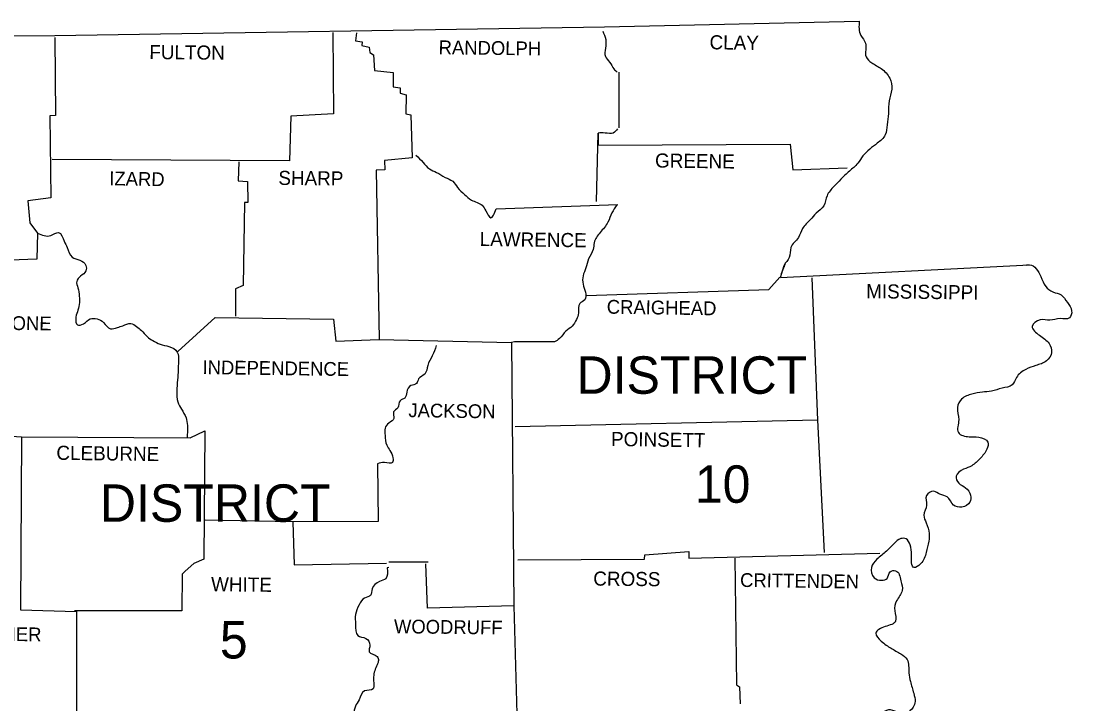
# Model space of a CAD drawing. Extents: x 21307 to 29830, y 1322443 to 1332359.
# Drawn here: x 25498.6 to 25818.7, y 1326299.6 to 1326507.6 of the extents above; entities that cross this region are included whole.
import ezdxf

# ---------------------------------------------------------------- set-up
doc = ezdxf.new("R2010")
doc.units = 0
doc.layers.add('R_Draft', color=7, linetype='Continuous')

msp = doc.modelspace()

# ---------------------------------------------------------------- linework, layer by layer
at = {"layer": 'R_Draft'}
for p, q in [((25729.86, 1326429.5), (25731.06, 1326433.2)), ((25730.16, 1326430.7), (25731.36, 1326433.6)), ((25610.66, 1326342.9), (25622.56, 1326342.9))]:
    msp.add_line(p, q, dxfattribs=at)
for points in [[(25205.26, 1326503), (25366.96, 1326502.9), (25508.86, 1326503.2), (25676.26, 1326505.8), (25753.86, 1326507.6)], [(25593.56, 1326504.1), (25593.76, 1326479.3), (25580.76, 1326478.6), (25580.36, 1326465), (25508.06, 1326465.4)], [(25600.76, 1326504), (25600.46, 1326501.6), (25602.46, 1326501.3), (25602.36, 1326500.1), (25604.66, 1326499.6), (25604.86, 1326498), (25605.96, 1326497.3), (25606.26, 1326492.5), (25611.96, 1326491.9), (25611.96, 1326487.6), (25614.06, 1326487.3), (25614.06, 1326485.6), (25615.86, 1326485.1), (25615.76, 1326479.3), (25617.36, 1326479), (25617.76, 1326465.9), (25609.26, 1326465.1), (25609.36, 1326462.3), (25606.76, 1326462.2), (25607.66, 1326410.6), (25647.96, 1326409.7), (25648.66, 1326329.5), (25622.36, 1326328.8), (25621.86, 1326342.3)], [(25508.86, 1326502.6), (25509.06, 1326478.8), (25507.36, 1326478.7), (25507.66, 1326453.8), (25500.66, 1326452.8), (25501.26, 1326446.1), (25503.66, 1326443), (25503.46, 1326435.1), (25489.86, 1326434.6), (25489.36, 1326422.4), (25476.96, 1326422), (25476.36, 1326407.2), (25477.06, 1326406), (25477.36, 1326382.4), (25498.76, 1326381), (25498.46, 1326328.3), (25515.46, 1326327.8), (25515.46, 1326274.2), (25502.06, 1326273.2), (25501.06, 1326261.4), (25478.56, 1326261.3)], [(25680.66, 1326492), (25680.66, 1326475.1)], [(25673.86, 1326452.6), (25674.36, 1326473.5), (25674.36, 1326469.8), (25732.86, 1326470.1), (25733.66, 1326462.3), (25750.16, 1326462.9)], [(25564.96, 1326464.7), (25564.76, 1326458.9), (25567.56, 1326458.7), (25567.66, 1326452.3), (25566.66, 1326452.3), (25566.26, 1326427.1), (25563.96, 1326426.1), (25563.96, 1326417.7)], [(25643.26, 1326450.4), (25680.36, 1326451.7)], [(25729.86, 1326429.5), (25805.76, 1326433.4)], [(25670.86, 1326424), (25726.36, 1326425.8), (25729.66, 1326429.6)], [(25739.46, 1326429.4), (25741.16, 1326386.1), (25743.16, 1326345.8)], [(25546.36, 1326407), (25557.76, 1326417.3), (25593.76, 1326416.8), (25594.46, 1326410.1), (25607.56, 1326410.6)], [(25661.06, 1326409.9), (25648.86, 1326409.9), (25647.96, 1326409.7)], [(25741.16, 1326386.1), (25649.06, 1326384)], [(25498.76, 1326381), (25550.16, 1326380.7), (25554.56, 1326382.8), (25554.26, 1326343.7), (25551.26, 1326342.4), (25548.56, 1326340.1), (25547.66, 1326339.2), (25547.56, 1326328), (25514.86, 1326328)], [(25607.16, 1326372.8), (25607.36, 1326355.2), (25581.36, 1326355.1), (25554.66, 1326355.6)], [(25581.36, 1326355.1), (25581.76, 1326342), (25609.86, 1326342.5)], [(25649.86, 1326343.5), (25688.46, 1326343.7), (25688.56, 1326345.1), (25701.96, 1326346.1), (25701.96, 1326344), (25760.16, 1326345.6)], [(25715.96, 1326344), (25716.46, 1326305.5), (25717.36, 1326304.9), (25717.66, 1326299.7)], [(25715.96, 1326344), (25716.46, 1326305.5), (25717.36, 1326304.9), (25717.66, 1326299.7)], [(25715.96, 1326344), (25716.46, 1326305.5), (25717.36, 1326304.9), (25717.66, 1326299.7)], [(25715.96, 1326344), (25716.46, 1326305.5), (25717.36, 1326304.9), (25717.66, 1326299.7)], [(25715.96, 1326344), (25716.46, 1326305.5), (25717.36, 1326304.9), (25717.66, 1326299.7)], [(25610.66, 1326341.2), (25610.16, 1326341.1)], [(25648.66, 1326329.5), (25650.16, 1326274.7), (25626.36, 1326274.6), (25626.26, 1326272.4), (25619.36, 1326272), (25618.76, 1326260.6), (25610.36, 1326260.6)]]:
    msp.add_lwpolyline(points, dxfattribs=at)
for points in [[(25753.86, 1326507.6), (25754.36, 1326503.2), (25755.76, 1326500.9), (25755.96, 1326496.7), (25757.66, 1326494.9), (25760.56, 1326493.1), (25763.16, 1326490.2), (25763.76, 1326486.8), (25762.96, 1326483.3), (25762.76, 1326479.4), (25762.36, 1326476), (25761.76, 1326472.9), (25759.36, 1326470.4), (25757.06, 1326468.6), (25754.96, 1326466.5), (25753.46, 1326464.3), (25750.86, 1326461.9), (25748.26, 1326459.4), (25746.16, 1326457.2), (25744.06, 1326454.4), (25743.06, 1326451.3), (25740.76, 1326449.1), (25738.96, 1326447.1), (25736.56, 1326444.4), (25735.36, 1326441.7), (25733.06, 1326438.6), (25732.56, 1326435.6), (25731.06, 1326433.2), (25730.96, 1326432.8)], [(25675.76, 1326504.5), (25676.66, 1326502), (25676.56, 1326499.3), (25676.56, 1326496.8), (25677.86, 1326495.1), (25679.16, 1326493), (25680.16, 1326492.1)], [(25680.26, 1326474.8), (25678.96, 1326473.5), (25676.46, 1326473.5), (25674.36, 1326473.5)], [(25618.86, 1326466.8), (25621.06, 1326464.5), (25622.96, 1326462.6), (25625.16, 1326461.5), (25627.76, 1326460), (25630.06, 1326458.8), (25631.56, 1326456.9), (25633.66, 1326454.8), (25635.76, 1326453.1), (25639.06, 1326451.5), (25640.16, 1326449.8), (25641.66, 1326447.7), (25643.26, 1326450.4)], [(25680.06, 1326451.6), (25678.56, 1326449.2), (25677.36, 1326446.4), (25674.96, 1326443.2), (25673.16, 1326440.1), (25672.86, 1326438), (25671.46, 1326435.2), (25670.66, 1326432.4), (25669.76, 1326430), (25669.76, 1326427.5), (25670.46, 1326425), (25670.26, 1326422.7), (25668.76, 1326421.6), (25668.36, 1326418.7), (25667.76, 1326416.7), (25666.46, 1326414.7), (25664.56, 1326413.2), (25662.56, 1326410.9), (25661.06, 1326409.9)], [(25503.66, 1326443), (25507.66, 1326442.3), (25510.06, 1326443.2), (25511.76, 1326440.6), (25512.66, 1326438.6), (25514.16, 1326435.7), (25516.56, 1326434.8), (25518.36, 1326433.2), (25518.36, 1326431.5), (25516.76, 1326429.9), (25515.56, 1326428.3), (25515.96, 1326426.4), (25516.36, 1326423.8), (25516.36, 1326421.3), (25515.76, 1326419), (25515.26, 1326416.9), (25515.76, 1326415.1), (25517.66, 1326415.4), (25519.66, 1326416.9), (25521.76, 1326416.9), (25523.76, 1326415.8), (25525.86, 1326413.9), (25527.96, 1326414.3), (25529.66, 1326414.8), (25532.06, 1326415.5), (25533.76, 1326414.6), (25535.26, 1326413.4), (25537.06, 1326411.5), (25538.76, 1326410.3), (25540.96, 1326409.2), (25543.66, 1326408.5), (25546.16, 1326406.8), (25546.56, 1326403.9), (25546.46, 1326401.4), (25546.26, 1326398.3), (25546.06, 1326394.9), (25546.36, 1326391.6), (25547.46, 1326389.4), (25548.86, 1326386.8), (25549.26, 1326384.4), (25549.16, 1326380.6)], [(25804.66, 1326433.3), (25805.76, 1326433.4), (25809.16, 1326429.8), (25810.66, 1326426.8), (25812.86, 1326425.1), (25815.36, 1326424.2), (25817.26, 1326421.9), (25818.56, 1326419.4), (25817.86, 1326417.2), (25815.06, 1326417), (25811.96, 1326416.5), (25808.96, 1326416.6), (25806.56, 1326414.6), (25808.76, 1326411.9), (25811.66, 1326409.4), (25812.46, 1326406.7), (25810.86, 1326404.1), (25807.66, 1326402.7), (25804.56, 1326401.5), (25801.76, 1326399.1), (25800.46, 1326396.8), (25797.36, 1326395.8), (25794.16, 1326394.9), (25791.36, 1326394.6), (25788.16, 1326394), (25785.06, 1326392.5), (25783.76, 1326389.9), (25784.16, 1326386.2), (25784.06, 1326382.3), (25787.36, 1326381), (25790.26, 1326380.9), (25793.06, 1326379.4), (25792.76, 1326377.2), (25790.66, 1326374.4), (25788.16, 1326372.2), (25785.66, 1326371.1), (25783.36, 1326369), (25784.16, 1326366.9), (25786.26, 1326365.5), (25787.76, 1326363.2), (25787.56, 1326361.1), (25785.16, 1326359.6), (25782.56, 1326360.2), (25780.66, 1326362.7), (25778.46, 1326363.5), (25776.56, 1326364.4), (25774.36, 1326363.1), (25774.36, 1326360.2), (25773.56, 1326357.1), (25774.26, 1326354.8), (25775.16, 1326351.6), (25775.06, 1326349.2), (25774.26, 1326345.8), (25772.56, 1326342.3), (25770.56, 1326341.2), (25769.76, 1326345), (25769.36, 1326348.1), (25768.16, 1326349.9), (25766.56, 1326350), (25764.46, 1326348.5), (25762.16, 1326346.2), (25759.26, 1326343.7), (25757.56, 1326341.2), (25758.46, 1326338.1), (25760.66, 1326337.3), (25762.36, 1326337.9), (25763.26, 1326339.9), (25764.96, 1326340.2), (25766.56, 1326337.1)], [(25625.06, 1326408.8), (25623.86, 1326405.7), (25622.46, 1326402.7), (25621.56, 1326400.1), (25619.66, 1326398.6), (25619.06, 1326397.2), (25617.36, 1326396.6), (25616.06, 1326394.6), (25615.46, 1326392.8), (25614.06, 1326392), (25613.36, 1326389.8), (25612.06, 1326388.6), (25612.16, 1326386.6), (25610.66, 1326385.2), (25609.46, 1326383.6), (25609.46, 1326381.4), (25609.96, 1326378.5), (25610.96, 1326376.8), (25611.86, 1326374.6), (25611.76, 1326373.2), (25609.26, 1326373.2), (25607.16, 1326372.8)], [(25610.16, 1326341.1), (25609.66, 1326337.8), (25607.76, 1326336.9), (25605.56, 1326334.7), (25605.06, 1326332.7), (25603.26, 1326331.9), (25601.56, 1326329.8), (25600.46, 1326326.9), (25600.46, 1326323.9), (25601.16, 1326320.5), (25603.66, 1326319.6), (25604.86, 1326317.6), (25604.66, 1326315.5), (25607.06, 1326314.1), (25607.46, 1326312.9), (25607.06, 1326311.6), (25605.96, 1326307.9), (25606.06, 1326305.4), (25605.86, 1326304.3), (25603.16, 1326303.6), (25601.56, 1326300.9), (25600.46, 1326299), (25600.06, 1326296.5), (25600.36, 1326294.7), (25599.56, 1326293.3), (25599.26, 1326291.2), (25598.26, 1326289.4), (25597.36, 1326287.7), (25598.36, 1326285.7), (25598.06, 1326284.3), (25597.46, 1326282.1), (25597.96, 1326281.4)], [(25766.56, 1326337.1), (25766.96, 1326334.2), (25765.26, 1326331.1), (25764.66, 1326328), (25764.96, 1326324.9), (25761.76, 1326323.2), (25758.96, 1326321.2), (25760.56, 1326318.8), (25763.56, 1326316.6), (25766.56, 1326314.9), (25768.46, 1326313.2), (25768.96, 1326309.1), (25769.46, 1326306.5), (25770.46, 1326302.9), (25770.86, 1326300.4), (25769.06, 1326297.4), (25766.96, 1326296.8), (25764.76, 1326297.5), (25762.16, 1326297.7), (25760.06, 1326295.7), (25758.56, 1326292.9), (25757.06, 1326290.1), (25755.96, 1326287.7), (25754.86, 1326285.1), (25752.66, 1326282.1), (25749.96, 1326281.6), (25746.76, 1326280.8), (25744.86, 1326278.6), (25745.16, 1326274.9), (25746.96, 1326272.4), (25748.36, 1326269.3), (25749.36, 1326266.6), (25748.86, 1326263.2), (25747.46, 1326260.7), (25745.66, 1326259.2), (25744.86, 1326256), (25743.56, 1326253.6), (25742.36, 1326252.8), (25739.96, 1326253), (25737.36, 1326253.5), (25735.16, 1326253.3), (25733.06, 1326252.2), (25730.96, 1326252.9), (25728.76, 1326255.3), (25726.96, 1326257.1), (25724.96, 1326257.8), (25722.86, 1326256.7), (25722.46, 1326253.4), (25723.46, 1326250), (25724.36, 1326245.4), (25723.46, 1326242.6), (25723.16, 1326238)]]:
    msp.add_spline(points, degree=3, dxfattribs=at)

# ---------------------------------------------------------------- texts
for s, height, rotation, p in [('CLAY', 4.299, 359.2258, (25708.26, 1326499)), ('FULTON', 4.3, 359.4996, (25537.66, 1326496)), ('RANDOLPH', 4.201, 359.2583, (25625.76, 1326497.5)), ('GREENE', 4.301, 359.2361, (25691.66, 1326463)), ('IZARD', 4.199, 358.9258, (25525.46, 1326457.6)), ('SHARP', 4.3, 359.3905, (25576.96, 1326457.7)), ('LAWRENCE', 4.301, 359.2678, (25638.26, 1326439.1)), ('MISSISSIPPI', 4.2995, 359.3097, (25755.96, 1326423.2)), ('CRAIGHEAD', 4.201, 359.1159, (25676.96, 1326418.5)), ('STONE', 4.199, 359.4001, (25488.56, 1326413.6)), ('INDEPENDENCE', 4.1993, 359.2187, (25553.86, 1326400.1)), ('JACKSON', 4.199, 359.1352, (25616.56, 1326387)), ('POINSETT', 4.3, 359.1987, (25678.26, 1326378.2)), ('CLEBURNE', 4.3, 359.2535, (25509.36, 1326374)), ('CROSS', 4.3, 359.3839, (25672.86, 1326335.7)), ('WHITE', 4.301, 359.3139, (25556.46, 1326334)), ('CRITTENDEN', 4.201, 359.213, (25717.56, 1326335.3)), ('WOODRUFF', 4.199, 359.2748, (25612.16, 1326321.2)), ('FAULKNER', 4.201, 359.2486, (25474.86, 1326319.1))]:
    msp.add_text(s, height=height, rotation=rotation, dxfattribs=at).set_placement(p)
for s, p in [('DISTRICT', (25667.76, 1326394.1)), ('10', (25703.79, 1326360.9)), ('DISTRICT', (25522.61, 1326355.11)), ('5', (25559.16, 1326313.5))]:
    msp.add_text(s, height=11.4, dxfattribs=at).set_placement(p)

doc.saveas('drawing.dxf')
